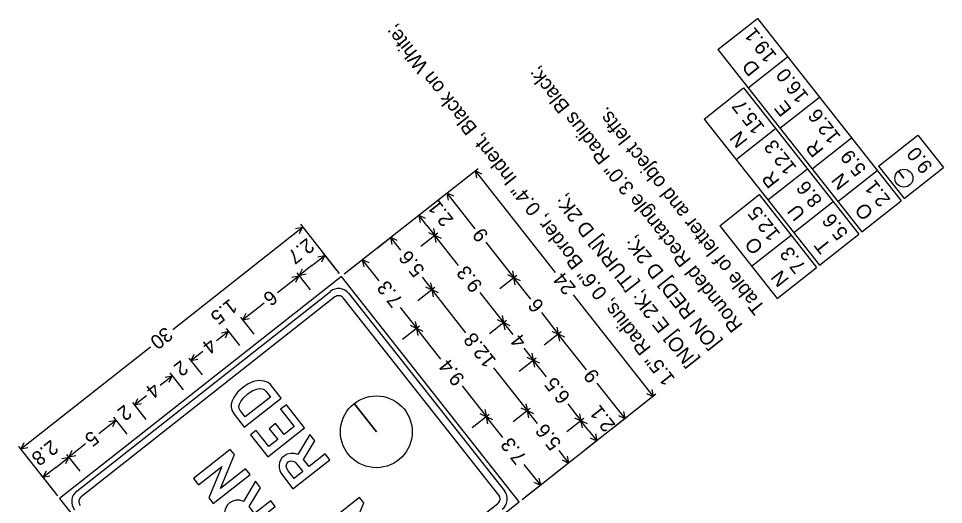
# Model space of a CAD drawing. Extents: x 672438 to 673763, y 1673171 to 1675010.
# Drawn here: x 672638.7 to 672697.6, y 1674769.5 to 1674800.5 of the extents above; entities that cross this region are included whole.
import ezdxf

# ---------------------------------------------------------------- set-up
doc = ezdxf.new("R2010")
doc.units = 0
doc.layers.add('C-TABL-BORD', color=7, linetype='Continuous')

msp = doc.modelspace()

# ---------------------------------------------------------------- linework, layer by layer
at = {"layer": 'C-TABL-BORD'}
for p, q in [((672683.213, 1674798.474), (672685.726, 1674800.455)), ((672685.726, 1674800.455), (672694.885, 1674788.838)), ((672683.213, 1674798.474), (672692.371, 1674786.856)), ((672685.134, 1674796.037), (672687.647, 1674798.019)), ((672682.334, 1674794.05), (672684.847, 1674796.031)), ((672684.847, 1674796.031), (672692.192, 1674786.715)), ((672687.164, 1674793.462), (672689.677, 1674795.444)), ((672682.334, 1674794.05), (672689.679, 1674784.733)), ((672684.364, 1674791.475), (672686.878, 1674793.456)), ((672689.203, 1674790.875), (672691.716, 1674792.857)), ((672693.434, 1674791.047), (672695.948, 1674793.028)), ((672695.948, 1674793.028), (672697.578, 1674790.961)), ((672667.944, 1674790.887), (672659.417, 1674784.164)), ((672672.861, 1674784.281), (672667.765, 1674790.745)), ((672668.179, 1674790.55), (672667.765, 1674790.745)), ((672667.857, 1674790.297), (672667.765, 1674790.745)), ((672686.395, 1674788.899), (672688.908, 1674790.88)), ((672690.839, 1674788.8), (672693.353, 1674790.781)), ((672693.434, 1674791.047), (672695.064, 1674788.979)), ((672694.702, 1674790.731), (672695.056, 1674790.282)), ((672695.056, 1674790.282), (672694.702, 1674790.731)), ((672695.064, 1674788.979), (672697.578, 1674790.961)), ((672666.149, 1674789.471), (672665.072, 1674788.622)), ((672667.758, 1674787.061), (672665.969, 1674789.33)), ((672666.383, 1674789.135), (672665.969, 1674789.33)), ((672666.062, 1674788.882), (672665.969, 1674789.33)), ((672683.325, 1674787.254), (672685.839, 1674789.235)), ((672685.839, 1674789.235), (672689.499, 1674784.592)), ((672688.036, 1674786.817), (672690.55, 1674788.798)), ((672692.371, 1674786.856), (672694.885, 1674788.838)), ((672664.354, 1674788.056), (672663.277, 1674787.207)), ((672664.679, 1674787.274), (672664.174, 1674787.915)), ((672664.588, 1674787.72), (672664.174, 1674787.915)), ((672664.267, 1674787.467), (672664.174, 1674787.915)), ((672648.494, 1674780.647), (672656.761, 1674787.164)), ((672656.313, 1674787.071), (672656.761, 1674787.164)), ((672656.566, 1674786.751), (672656.761, 1674787.164)), ((672656.619, 1674787.344), (672659.096, 1674784.202)), ((672664.679, 1674787.274), (672665.184, 1674786.634)), ((672665.091, 1674787.082), (672665.184, 1674786.634)), ((672683.325, 1674787.254), (672686.986, 1674782.611)), ((672662.559, 1674786.641), (672661.481, 1674785.792)), ((672663.011, 1674785.698), (672662.379, 1674786.499)), ((672662.793, 1674786.304), (672662.379, 1674786.499)), ((672662.472, 1674786.052), (672662.379, 1674786.499)), ((672665.363, 1674786.776), (672664.286, 1674785.926)), ((672665.363, 1674786.776), (672664.286, 1674785.926)), ((672664.77, 1674786.829), (672665.184, 1674786.634)), ((672666.699, 1674784.712), (672665.184, 1674786.634)), ((672665.598, 1674786.439), (672665.184, 1674786.634)), ((672665.277, 1674786.186), (672665.184, 1674786.634)), ((672685.359, 1674784.675), (672687.872, 1674786.656)), ((672689.679, 1674784.733), (672692.192, 1674786.715)), ((672668.426, 1674786.213), (672670.215, 1674783.944)), ((672657.353, 1674784.72), (672658.176, 1674785.369)), ((672657.728, 1674785.276), (672658.176, 1674785.369)), ((672657.981, 1674784.955), (672658.176, 1674785.369)), ((672658.034, 1674785.549), (672658.884, 1674784.471)), ((672660.763, 1674785.226), (672659.686, 1674784.376)), ((672657.353, 1674784.72), (672656.53, 1674784.072)), ((672661.633, 1674783.753), (672660.584, 1674785.084)), ((672660.998, 1674784.889), (672660.584, 1674785.084)), ((672660.677, 1674784.636), (672660.584, 1674785.084)), ((672655.167, 1674782.997), (672656.53, 1674784.072)), ((672656.083, 1674783.979), (672656.53, 1674784.072)), ((672656.335, 1674783.658), (672656.53, 1674784.072)), ((672656.389, 1674784.251), (672657.238, 1674783.174)), ((672656.389, 1674784.251), (672657.238, 1674783.174)), ((672656.725, 1674784.485), (672656.53, 1674784.072)), ((672656.978, 1674784.165), (672656.53, 1674784.072)), ((672670.395, 1674784.086), (672669.318, 1674783.237)), ((672670.395, 1674784.086), (672669.318, 1674783.237)), ((672669.801, 1674784.139), (672670.215, 1674783.944)), ((672670.122, 1674784.392), (672670.215, 1674783.944)), ((672686.986, 1674782.611), (672689.499, 1674784.592)), ((672664.37, 1674783.974), (672665.002, 1674783.172)), ((672664.909, 1674783.62), (672665.002, 1674783.172)), ((672671.29, 1674782.58), (672670.215, 1674783.944)), ((672670.629, 1674783.749), (672670.215, 1674783.944)), ((672670.308, 1674783.496), (672670.215, 1674783.944)), ((672665.182, 1674783.314), (672664.104, 1674782.465)), ((672665.182, 1674783.314), (672664.104, 1674782.465)), ((672664.588, 1674783.367), (672665.002, 1674783.172)), ((672667.165, 1674780.429), (672665.002, 1674783.172)), ((672665.416, 1674782.977), (672665.002, 1674783.172)), ((672665.095, 1674782.724), (672665.002, 1674783.172)), ((672668.046, 1674783.003), (672669.562, 1674781.081)), ((672673.991, 1674782.847), (672679.087, 1674776.383)), ((672654.304, 1674782.316), (672652.94, 1674781.241)), ((672662.978, 1674782.047), (672664.028, 1674780.716)), ((672671.971, 1674781.718), (672673.046, 1674780.354)), ((672652.798, 1674781.421), (672653.648, 1674780.344)), ((672653.135, 1674781.655), (672652.94, 1674781.241)), ((672653.388, 1674781.334), (672652.94, 1674781.241)), ((672663.935, 1674781.164), (672664.028, 1674780.716)), ((672669.741, 1674781.222), (672668.664, 1674780.373)), ((672669.148, 1674781.276), (672669.562, 1674781.081)), ((672669.469, 1674781.529), (672669.562, 1674781.081)), ((672670.161, 1674780.321), (672669.562, 1674781.081)), ((672669.976, 1674780.886), (672669.562, 1674781.081)), ((672669.654, 1674780.633), (672669.562, 1674781.081)), ((672651.282, 1674779.934), (672652.042, 1674780.534)), ((672651.595, 1674780.441), (672652.042, 1674780.534)), ((672651.847, 1674780.12), (672652.042, 1674780.534)), ((672651.901, 1674780.713), (672652.75, 1674779.636)), ((672664.207, 1674780.857), (672663.13, 1674780.008)), ((672664.207, 1674780.857), (672663.13, 1674780.008)), ((672663.614, 1674780.911), (672664.028, 1674780.716)), ((672665.571, 1674778.758), (672664.028, 1674780.716)), ((672664.441, 1674780.521), (672664.028, 1674780.716)), ((672664.121, 1674780.268), (672664.028, 1674780.716)), ((672673.225, 1674780.495), (672672.148, 1674779.646)), ((672672.632, 1674780.549), (672673.046, 1674780.354)), ((672672.953, 1674780.802), (672673.046, 1674780.354)), ((672674.835, 1674778.085), (672673.046, 1674780.354)), ((672673.46, 1674780.159), (672673.046, 1674780.354)), ((672673.139, 1674779.906), (672673.046, 1674780.354)), ((672647.075, 1674779.528), (672638.808, 1674773.012)), ((672670.85, 1674779.447), (672671.449, 1674778.687)), ((672649.507, 1674778.826), (672650.356, 1674777.749)), ((672650.409, 1674779.246), (672649.649, 1674778.647)), ((672649.844, 1674779.06), (672649.649, 1674778.647)), ((672650.096, 1674778.74), (672649.649, 1674778.647)), ((672671.628, 1674778.829), (672670.551, 1674777.98)), ((672671.035, 1674778.882), (672671.449, 1674778.687)), ((672671.356, 1674779.135), (672671.449, 1674778.687)), ((672668.915, 1674778.208), (672671.078, 1674775.465)), ((672672.29, 1674777.62), (672671.449, 1674778.687)), ((672671.863, 1674778.492), (672671.449, 1674778.687)), ((672671.542, 1674778.239), (672671.449, 1674778.687)), ((672647.692, 1674777.104), (672648.452, 1674777.703)), ((672648.004, 1674777.61), (672648.452, 1674777.703)), ((672648.257, 1674777.289), (672648.452, 1674777.703)), ((672648.31, 1674777.883), (672649.159, 1674776.805)), ((672666.919, 1674777.049), (672668.462, 1674775.091)), ((672675.503, 1674777.237), (672677.292, 1674774.968)), ((672646.818, 1674776.415), (672646.058, 1674775.816)), ((672679.266, 1674776.525), (672670.739, 1674769.802)), ((672678.673, 1674776.578), (672679.087, 1674776.383)), ((672678.994, 1674776.831), (672679.087, 1674776.383)), ((672645.917, 1674775.996), (672646.766, 1674774.918)), ((672646.253, 1674776.23), (672646.058, 1674775.816)), ((672646.506, 1674775.909), (672646.058, 1674775.816)), ((672660.042, 1674775.924), (672661.458, 1674774.129)), ((672661.458, 1674774.129), (672660.042, 1674775.924)), ((672670.985, 1674775.913), (672671.078, 1674775.465)), ((672673.646, 1674775.9), (672674.487, 1674774.833)), ((672668.642, 1674775.232), (672667.565, 1674774.383)), ((672668.048, 1674775.286), (672668.462, 1674775.091)), ((672668.369, 1674775.539), (672668.462, 1674775.091)), ((672671.258, 1674775.606), (672670.181, 1674774.757)), ((672670.665, 1674775.66), (672671.078, 1674775.465)), ((672671.71, 1674774.663), (672671.078, 1674775.465)), ((672671.492, 1674775.27), (672671.078, 1674775.465)), ((672671.171, 1674775.017), (672671.078, 1674775.465)), ((672674.394, 1674775.281), (672674.487, 1674774.833)), ((672677.199, 1674775.416), (672677.292, 1674774.968)), ((672643.791, 1674774.029), (672644.861, 1674774.873)), ((672644.414, 1674774.78), (672644.861, 1674774.873)), ((672644.666, 1674774.459), (672644.861, 1674774.873)), ((672644.72, 1674775.052), (672645.569, 1674773.975)), ((672669.512, 1674773.759), (672668.462, 1674775.091)), ((672668.876, 1674774.896), (672668.462, 1674775.091)), ((672668.555, 1674774.643), (672668.462, 1674775.091)), ((672674.666, 1674774.975), (672673.589, 1674774.126)), ((672674.073, 1674775.028), (672674.487, 1674774.833)), ((672674.992, 1674774.193), (672674.487, 1674774.833)), ((672674.901, 1674774.639), (672674.487, 1674774.833)), ((672674.58, 1674774.386), (672674.487, 1674774.833)), ((672677.471, 1674775.11), (672676.394, 1674774.261)), ((672676.878, 1674775.163), (672677.292, 1674774.968)), ((672674.992, 1674774.193), (672675.496, 1674773.553)), ((672675.404, 1674774.001), (672675.496, 1674773.553)), ((672639.003, 1674773.425), (672638.808, 1674773.012)), ((672675.676, 1674773.694), (672674.599, 1674772.845)), ((672675.083, 1674773.748), (672675.496, 1674773.553)), ((672638.667, 1674773.191), (672641.144, 1674770.05)), ((672639.256, 1674773.105), (672638.808, 1674773.012)), ((672642.939, 1674773.357), (672641.869, 1674772.514)), ((672642.064, 1674772.927), (672641.869, 1674772.514)), ((672673.069, 1674772.939), (672673.701, 1674772.138)), ((672641.047, 1674771.865), (672641.869, 1674772.514)), ((672641.422, 1674772.421), (672641.869, 1674772.514)), ((672641.674, 1674772.1), (672641.869, 1674772.514)), ((672641.728, 1674772.693), (672642.577, 1674771.616)), ((672642.317, 1674772.607), (672641.869, 1674772.514)), ((672673.881, 1674772.279), (672672.804, 1674771.43)), ((672673.287, 1674772.333), (672673.701, 1674772.138)), ((672673.608, 1674772.585), (672673.701, 1674772.138)), ((672641.047, 1674771.865), (672640.224, 1674771.216)), ((672670.856, 1674772.054), (672671.906, 1674770.722)), ((672640.082, 1674771.396), (672640.931, 1674770.319)), ((672640.419, 1674771.63), (672640.224, 1674771.216)), ((672640.672, 1674771.309), (672640.224, 1674771.216)), ((672671.813, 1674771.17), (672671.906, 1674770.722)), ((672672.085, 1674770.864), (672671.008, 1674770.015)), ((672671.492, 1674770.917), (672671.906, 1674770.722))]:
    msp.add_line(p, q, dxfattribs=at)
for points in [[(672670.56, 1674769.661), (672659.237, 1674784.023), (672641.285, 1674769.87), (672652.607, 1674755.508), (672670.56, 1674769.661), (672670.56, 1674769.661)], [(672642.372, 1674770.338), (672658.528, 1674783.076)], [(672659.706, 1674782.936), (672669.613, 1674770.37)], [(672658.812, 1674782.717), (672642.655, 1674769.979)], [(672669.253, 1674770.087), (672659.347, 1674782.653)], [(672652.4, 1674775.252), (672653.049, 1674774.428), (672655.396, 1674776.279), (672654.717, 1674777.14), (672654.558, 1674777.27), (672654.317, 1674777.358), (672653.982, 1674777.39), (672653.637, 1674777.331), (672653.284, 1674777.18), (672652.924, 1674776.939), (672652.618, 1674776.649), (672652.377, 1674776.309), (672652.275, 1674776.092), (672652.218, 1674775.887), (672652.209, 1674775.695), (672652.246, 1674775.514), (672652.4, 1674775.252)], [(672654.42, 1674776.724), (672654.72, 1674776.343), (672653.111, 1674775.074), (672652.783, 1674775.49), (672652.719, 1674775.61), (672652.704, 1674775.747), (672652.739, 1674775.898), (672652.821, 1674776.064), (672653.009, 1674776.306), (672653.262, 1674776.537), (672653.552, 1674776.729), (672653.841, 1674776.85), (672654.024, 1674776.885), (672654.181, 1674776.876), (672654.313, 1674776.822), (672654.42, 1674776.724)], [(672658.491, 1674772.353), (672658.201, 1674772.722), (672657.171, 1674771.91), (672656.817, 1674772.359), (672657.545, 1674773.554), (672657.222, 1674773.963), (672656.457, 1674772.681), (672656.237, 1674772.751), (672656.002, 1674772.757), (672655.775, 1674772.701), (672655.576, 1674772.585), (672655.448, 1674772.462), (672655.353, 1674772.324), (672655.291, 1674772.172), (672655.261, 1674772.004), (672655.265, 1674771.833), (672655.302, 1674771.667), (672655.37, 1674771.509), (672655.47, 1674771.357), (672656.146, 1674770.504), (672658.491, 1674772.353)], [(672656.774, 1674771.597), (672656.222, 1674771.161), (672655.836, 1674771.651), (672655.752, 1674771.795), (672655.722, 1674771.949), (672655.752, 1674772.093), (672655.846, 1674772.209), (672655.989, 1674772.276), (672656.145, 1674772.264), (672656.284, 1674772.192), (672656.403, 1674772.067), (672656.774, 1674771.597)], [(672655.023, 1674769.367), (672654.733, 1674769.735), (672653.703, 1674768.924), (672653.349, 1674769.373), (672654.077, 1674770.568), (672653.755, 1674770.977), (672652.989, 1674769.695), (672652.769, 1674769.765), (672652.534, 1674769.771), (672652.308, 1674769.715), (672652.108, 1674769.598), (672651.98, 1674769.476), (672651.885, 1674769.338), (672651.823, 1674769.186), (672651.793, 1674769.018), (672651.798, 1674768.846), (672651.834, 1674768.681), (672651.902, 1674768.523), (672652.002, 1674768.371), (672652.678, 1674767.518), (672655.023, 1674769.367)], [(672653.033, 1674756.814), (672669.19, 1674769.552)]]:
    msp.add_lwpolyline(points, dxfattribs=at)
for points in [[(672656.887, 1674774.388), (672655.73, 1674775.856), (672655.362, 1674775.566), (672656.232, 1674774.462), (672655.587, 1674773.954), (672655.039, 1674774.65), (672654.624, 1674774.324), (672655.173, 1674773.628), (672654.62, 1674773.192), (672653.811, 1674774.219), (672653.443, 1674773.929), (672654.54, 1674772.537)], [(672653.419, 1674771.402), (672653.129, 1674771.77), (672651.527, 1674770.507), (672652.414, 1674772.678), (672652.151, 1674773.011), (672649.803, 1674771.161), (672650.128, 1674770.748), (672651.622, 1674771.925), (672650.782, 1674769.919), (672651.072, 1674769.551)], [(672661.661, 1674768.332), (672661.371, 1674768.7), (672659.769, 1674767.437), (672660.656, 1674769.608), (672660.393, 1674769.941), (672658.045, 1674768.091), (672658.37, 1674767.678), (672659.863, 1674768.855), (672659.024, 1674766.85), (672659.314, 1674766.481)]]:
    msp.add_lwpolyline(points, close=True, dxfattribs=at)
for centre, radius in [((672695.056, 1674790.282), 0.571), ((672661.458, 1674774.129), 2.286)]:
    msp.add_circle(centre, radius, dxfattribs=at)
for centre, radius, start, end in [((672659.047, 1674782.417), 0.838, 38.2506, 128.25081), ((672659.047, 1674782.417), 0.381, 38.2506, 128.25081), ((672642.89, 1674769.68), 0.838, 128.25054, 218.25075), ((672642.89, 1674769.68), 0.381, 128.25054, 218.25075), ((672668.954, 1674769.851), 0.381, 308.25039, 38.2506), ((672668.954, 1674769.851), 0.838, 308.25039, 38.2506)]:
    msp.add_arc(centre, radius, start, end, dxfattribs=at)

# ---------------------------------------------------------------- texts
for s, height, rotation, p in [('1.5" Radius, 0.6" Border, 0.4" Indent, Black on White; ', 0.9144, 128.25054, (672680.523, 1674777.516)), ('19.1', 0.9144, 128.25054, (672687.005, 1674798.095)), ('D', 0.914, 128.25054, (672685.928, 1674797.245)), ('Rounded Rectangle 3.0" Radius Black; ', 0.9144, 128.25054, (672684.832, 1674780.912)), ('16.0', 0.9144, 128.25054, (672689.035, 1674795.52)), ('E', 0.914, 128.25054, (672687.958, 1674794.67)), ('Table of letter and object lefts.', 0.9144, 128.25054, (672686.268, 1674782.044)), ('15.7', 0.9144, 128.25054, (672686.236, 1674793.532)), ('12.6', 0.9144, 128.25054, (672691.074, 1674792.933)), ('N', 0.914, 128.25054, (672685.158, 1674792.683)), ('12.3', 0.9144, 128.25054, (672688.266, 1674790.956)), ('R', 0.914, 128.25054, (672689.997, 1674792.083)), ('5.9', 0.9144, 128.25054, (672692.71, 1674790.857)), ('9.0', 0.9144, 128.25054, (672696.936, 1674791.037)), ('R', 0.914, 128.25054, (672687.189, 1674790.107)), ('N', 0.914, 128.25054, (672691.633, 1674790.008)), ('8.6', 0.9144, 128.25054, (672689.908, 1674788.874)), ('2.1', 0.9144, 128.25054, (672694.243, 1674788.914)), ('[NO] E 2K; [TURN] D 2K; ', 0.9144, 128.25054, (672681.959, 1674778.648)), ('2.1', 0.9144, 128.25054, (672666.419, 1674787.652)), ('12.5', 0.9144, 128.25054, (672687.23, 1674786.732)), ('U', 0.914, 128.25054, (672688.831, 1674788.025)), ('O', 0.914, 128.25054, (672693.166, 1674788.065)), ('5.6', 0.9144, 128.25054, (672691.55, 1674786.791)), ('9', 0.914, 128.25054, (672668.644, 1674786.676)), ('2.7', 0.9144, 218.25075, (672657.045, 1674786.515)), ('[ON RED] D 2K; ', 0.9144, 128.25054, (672683.395, 1674779.78)), ('O', 0.914, 128.25054, (672686.153, 1674785.883)), ('7.3', 0.9144, 128.25054, (672688.857, 1674784.668)), ('T', 0.914, 128.25054, (672690.473, 1674785.942)), ('5.6', 0.9144, 128.25054, (672664.587, 1674784.437)), ('9.3', 0.9144, 128.25054, (672668.264, 1674783.466)), ('24', 0.9144, 128.25054, (672674.208, 1674783.31)), ('N', 0.914, 128.25054, (672687.78, 1674783.819)), ('7.3', 0.9144, 128.25054, (672663.195, 1674782.51)), ('6', 0.914, 218.25075, (672654.704, 1674783.214)), ('1.5', 0.9144, 218.25075, (672652.143, 1674782.651)), ('6', 0.914, 128.25054, (672672.188, 1674782.18)), ('30', 0.9144, 218.25075, (672648.032, 1674780.865)), ('4', 0.914, 218.25075, (672650.82, 1674780.152)), ('12.8', 0.9144, 128.25054, (672669.133, 1674778.671)), ('4', 0.914, 128.25054, (672671.067, 1674779.91)), ('9.4', 0.9144, 128.25054, (672667.136, 1674777.511)), ('2', 0.914, 218.25075, (672649.014, 1674778.728)), ('6.5', 0.9144, 128.25054, (672673.863, 1674776.363)), ('9', 0.914, 128.25054, (672675.72, 1674777.7)), ('4', 0.914, 218.25075, (672647.229, 1674777.321)), ('2', 0.914, 218.25075, (672645.423, 1674775.898)), ('2.1', 0.9144, 128.25054, (672676.731, 1674774.571)), ('5.6', 0.9144, 128.25054, (672673.287, 1674773.402)), ('5', 0.914, 218.25075, (672643.329, 1674774.247)), ('2.8', 0.9144, 218.25075, (672640.74, 1674773.661)), ('7.3', 0.9144, 128.25054, (672671.074, 1674772.516))]:
    msp.add_text(s, height=height, rotation=rotation, dxfattribs=at).set_placement(p)

doc.saveas('drawing.dxf')
